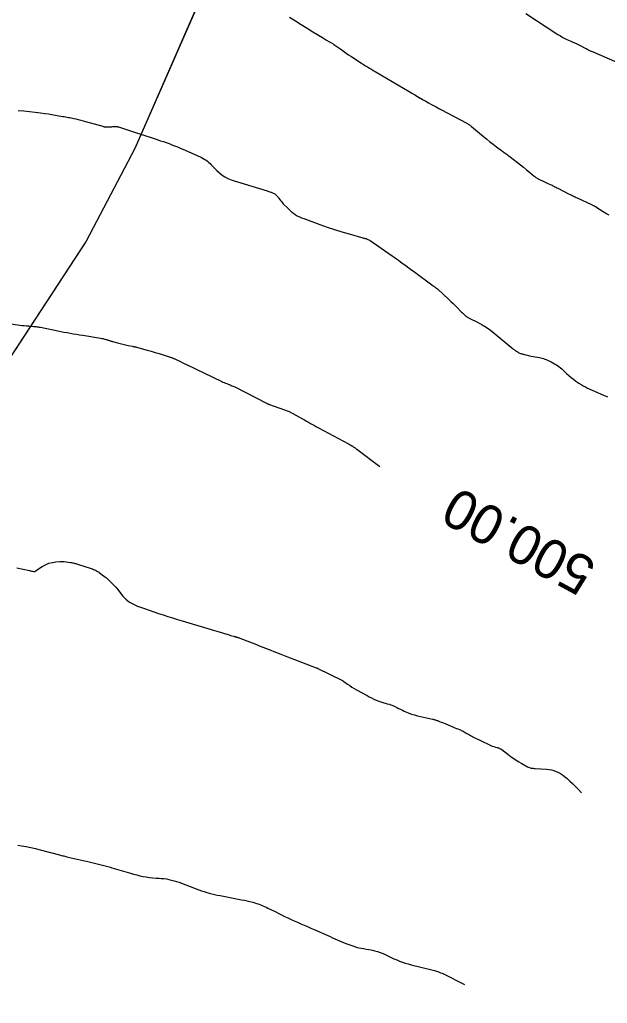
# Model space of a CAD drawing. Extents: x -629976 to -626966, y -1086511 to -1082952.
# Drawn here: x -628393.8 to -628244, y -1086175.2 to -1085924.7 of the extents above; entities that cross this region are included whole.
import ezdxf

# ---------------------------------------------------------------- set-up
doc = ezdxf.new("R2010")
doc.units = 0
for name, color, linetype in [('01_OBVOD PÚ', 7, 'Continuous'), ('01_SPRÁV_HRANICE', 7, 'Continuous'), ('01_VRSTEVNICE', 7, 'Continuous'), ('02_KULTURY STAV', 7, 'Continuous'), ('04_ZPF_OP_ORGAN', 7, 'Continuous')]:
    doc.layers.add(name, color=color, linetype=linetype)

msp = doc.modelspace()

# ---------------------------------------------------------------- linework, layer by layer
at = {"layer": '01_OBVOD PÚ'}
msp.add_lwpolyline([(-628341.94, -1085906.1), (-628364.43, -1085957.53), (-628376.86, -1085981.07), (-628416.21, -1086041.23), (-628422.26, -1086053.45), (-628443.41, -1086096.14), (-628453.2, -1086122.49), (-628455.25, -1086128.01), (-628487.12, -1086214.31), (-628510.82, -1086282.32), (-628525.65, -1086314.27), (-628531.32, -1086323.89), (-628534.4, -1086329.12), (-628536.6, -1086332.86), (-628546.36, -1086361.96)], dxfattribs=at)
at = {"layer": '01_SPRÁV_HRANICE'}
for p, q in [((-628341.94, -1085906.1), (-628364.43, -1085957.53)), ((-628364.43, -1085957.53), (-628376.86, -1085981.07)), ((-628376.86, -1085981.07), (-628416.21, -1086041.23))]:
    msp.add_line(p, q, dxfattribs=at)
at = {"layer": '01_VRSTEVNICE'}
for points in [[(-628325.01, -1085924.07), (-628323.53, -1085925.02), (-628322.03, -1085925.95), (-628320.54, -1085926.88), (-628319.03, -1085927.79), (-628316.62, -1085929.24), (-628316.09, -1085929.56), (-628315.56, -1085929.88), (-628315.02, -1085930.21), (-628314.49, -1085930.53), (-628313.93, -1085930.87), (-628313.68, -1085931.03), (-628313.43, -1085931.19), (-628313.18, -1085931.36), (-628312.93, -1085931.53), (-628312.69, -1085931.7), (-628312.45, -1085931.87), (-628312.21, -1085932.04), (-628311.96, -1085932.22), (-628311.23, -1085932.75), (-628310.61, -1085933.18), (-628309.99, -1085933.61), (-628309.37, -1085934.02), (-628308.74, -1085934.43), (-628307.12, -1085935.48), (-628306.63, -1085935.79), (-628306.14, -1085936.1), (-628305.65, -1085936.41), (-628305.15, -1085936.71), (-628304.66, -1085937.01), (-628304.16, -1085937.31), (-628303.66, -1085937.61), (-628303.16, -1085937.9), (-628294.5, -1085943.02), (-628293.81, -1085943.43), (-628293.11, -1085943.84), (-628292.41, -1085944.25), (-628291.71, -1085944.66), (-628291.63, -1085944.7), (-628290.97, -1085945.08), (-628290.3, -1085945.46), (-628289.63, -1085945.83), (-628288.96, -1085946.19), (-628288.29, -1085946.56), (-628287.62, -1085946.92), (-628286.94, -1085947.28), (-628286.27, -1085947.64), (-628280.03, -1085950.95), (-628279.85, -1085951.05), (-628279.68, -1085951.16), (-628279.5, -1085951.27), (-628279.33, -1085951.38), (-628279.16, -1085951.5), (-628279, -1085951.63), (-628278.83, -1085951.75), (-628278.67, -1085951.88), (-628275.58, -1085954.45), (-628274.76, -1085955.12), (-628273.93, -1085955.78), (-628273.09, -1085956.42), (-628272.24, -1085957.06), (-628271.02, -1085957.97), (-628270.78, -1085958.14), (-628270.54, -1085958.32), (-628270.3, -1085958.5), (-628270.06, -1085958.67), (-628269.82, -1085958.85), (-628269.58, -1085959.03), (-628269.34, -1085959.21), (-628269.1, -1085959.39), (-628266.94, -1085961.08), (-628266.17, -1085961.68), (-628265.4, -1085962.29), (-628264.64, -1085962.91), (-628263.88, -1085963.53), (-628262.64, -1085964.55), (-628262.5, -1085964.66), (-628262.36, -1085964.77), (-628262.22, -1085964.88), (-628262.08, -1085964.98), (-628261.93, -1085965.08), (-628261.78, -1085965.17), (-628261.63, -1085965.25), (-628261.47, -1085965.33), (-628260.18, -1085965.93), (-628259.84, -1085966.08), (-628259.49, -1085966.24), (-628259.15, -1085966.4), (-628258.8, -1085966.56), (-628258.62, -1085966.64), (-628258.37, -1085966.76), (-628258.12, -1085966.88), (-628257.87, -1085967.01), (-628257.62, -1085967.13), (-628257.37, -1085967.26), (-628257.12, -1085967.38), (-628256.87, -1085967.51), (-628256.62, -1085967.64), (-628253.76, -1085969.09), (-628253.51, -1085969.22), (-628253.26, -1085969.34), (-628253.01, -1085969.47), (-628252.75, -1085969.59), (-628252.5, -1085969.71), (-628252.25, -1085969.83), (-628252, -1085969.95), (-628251.74, -1085970.06), (-628248.03, -1085971.8), (-628247.9, -1085971.86), (-628247.78, -1085971.92), (-628247.65, -1085971.98), (-628247.53, -1085972.04), (-628247.36, -1085972.12), (-628247.32, -1085972.14), (-628247.28, -1085972.16), (-628247.24, -1085972.18), (-628247.2, -1085972.2), (-628247.16, -1085972.22), (-628247.11, -1085972.25), (-628247.07, -1085972.27), (-628247.03, -1085972.29), (-628246.96, -1085972.33), (-628246.89, -1085972.38), (-628246.82, -1085972.42), (-628246.74, -1085972.47), (-628246.67, -1085972.51), (-628245.12, -1085973.51), (-628244.63, -1085973.82), (-628244.15, -1085974.13), (-628243.66, -1085974.43)], [(-628264.83, -1085923.08), (-628256.92, -1085928.26), (-628256.61, -1085928.46), (-628256.29, -1085928.65), (-628255.97, -1085928.84), (-628255.65, -1085929.03), (-628255.33, -1085929.2), (-628255, -1085929.38), (-628254.66, -1085929.54), (-628254.32, -1085929.7), (-628253.47, -1085930.08), (-628252.79, -1085930.39), (-628252.11, -1085930.71), (-628251.44, -1085931.04), (-628250.77, -1085931.37), (-628249.64, -1085931.93), (-628249.54, -1085931.99), (-628249.43, -1085932.04), (-628249.33, -1085932.1), (-628249.23, -1085932.16), (-628249.12, -1085932.22), (-628249.02, -1085932.27), (-628248.92, -1085932.33), (-628248.81, -1085932.38), (-628248.7, -1085932.44), (-628248.54, -1085932.52), (-628248.37, -1085932.6), (-628248.21, -1085932.67), (-628248.04, -1085932.74), (-628239.69, -1085936.32)], [(-628394.18, -1085947.8), (-628392.74, -1085947.93), (-628391.3, -1085948.07), (-628389.87, -1085948.24), (-628388.44, -1085948.43), (-628387.34, -1085948.58), (-628386.46, -1085948.71), (-628385.58, -1085948.85), (-628384.7, -1085948.99), (-628383.82, -1085949.15), (-628382.79, -1085949.33), (-628382.43, -1085949.39), (-628382.07, -1085949.46), (-628381.72, -1085949.52), (-628381.36, -1085949.58), (-628381, -1085949.64), (-628380.65, -1085949.71), (-628380.29, -1085949.78), (-628379.94, -1085949.86), (-628379.43, -1085949.97), (-628378.83, -1085950.11), (-628378.22, -1085950.26), (-628377.62, -1085950.42), (-628377.02, -1085950.59), (-628372.62, -1085951.85), (-628372.49, -1085951.88), (-628372.37, -1085951.91), (-628372.24, -1085951.94), (-628372.11, -1085951.97), (-628371.98, -1085951.98), (-628371.85, -1085951.99), (-628371.72, -1085952), (-628371.58, -1085952), (-628371.23, -1085951.98), (-628370.92, -1085951.96), (-628370.62, -1085951.95), (-628370.31, -1085951.94), (-628370, -1085951.92), (-628369.36, -1085951.89), (-628369.26, -1085951.89), (-628369.16, -1085951.9), (-628369.06, -1085951.91), (-628368.96, -1085951.92), (-628368.86, -1085951.94), (-628368.76, -1085951.96), (-628368.66, -1085951.99), (-628368.56, -1085952.02), (-628364.22, -1085953.42), (-628362.91, -1085953.85), (-628361.61, -1085954.27), (-628360.31, -1085954.7), (-628359.01, -1085955.12), (-628357.86, -1085955.51), (-628357.14, -1085955.75), (-628356.42, -1085956), (-628355.7, -1085956.26), (-628354.99, -1085956.53), (-628354.29, -1085956.81), (-628353.58, -1085957.09), (-628352.88, -1085957.39), (-628352.19, -1085957.69), (-628347.79, -1085959.64), (-628347.4, -1085959.83), (-628347.01, -1085960.03), (-628346.63, -1085960.26), (-628346.26, -1085960.49), (-628345.91, -1085960.75), (-628345.58, -1085961.03), (-628345.26, -1085961.33), (-628344.96, -1085961.65), (-628344.9, -1085961.71), (-628344.58, -1085962.07), (-628344.24, -1085962.42), (-628343.9, -1085962.75), (-628343.55, -1085963.08), (-628342.86, -1085963.71), (-628342.18, -1085964.25), (-628341.47, -1085964.73), (-628340.71, -1085965.12), (-628339.91, -1085965.45), (-628339.08, -1085965.72), (-628338.25, -1085965.99), (-628337.42, -1085966.25), (-628336.58, -1085966.51), (-628330.74, -1085968.27), (-628330.5, -1085968.34), (-628330.26, -1085968.42), (-628330.03, -1085968.5), (-628329.79, -1085968.58), (-628329.73, -1085968.6), (-628329.53, -1085968.68), (-628329.34, -1085968.76), (-628329.15, -1085968.86), (-628328.96, -1085968.97), (-628328.78, -1085969.08), (-628328.61, -1085969.21), (-628328.45, -1085969.35), (-628328.31, -1085969.51), (-628328.3, -1085969.51), (-628328.16, -1085969.68), (-628328.02, -1085969.84), (-628327.88, -1085970.01), (-628327.75, -1085970.18), (-628327.56, -1085970.43), (-628327.33, -1085970.72), (-628327.09, -1085971), (-628326.85, -1085971.28), (-628326.59, -1085971.55), (-628325.39, -1085972.79), (-628324.96, -1085973.21), (-628324.51, -1085973.6), (-628324.04, -1085973.96), (-628323.54, -1085974.3), (-628323.03, -1085974.61), (-628322.5, -1085974.89), (-628321.96, -1085975.14), (-628321.4, -1085975.36), (-628317.27, -1085976.86), (-628315.42, -1085977.5), (-628313.57, -1085978.13), (-628311.7, -1085978.71), (-628309.83, -1085979.27), (-628306.29, -1085980.28), (-628306.17, -1085980.31), (-628306.06, -1085980.33), (-628305.95, -1085980.36), (-628305.83, -1085980.38), (-628305.72, -1085980.4), (-628305.61, -1085980.43), (-628305.49, -1085980.46), (-628305.38, -1085980.5), (-628305.22, -1085980.56), (-628305.03, -1085980.64), (-628304.84, -1085980.72), (-628304.66, -1085980.83), (-628304.49, -1085980.94), (-628298.85, -1085984.82), (-628298.31, -1085985.19), (-628297.77, -1085985.57), (-628297.24, -1085985.96), (-628296.71, -1085986.35), (-628296.38, -1085986.6), (-628296.01, -1085986.87), (-628295.65, -1085987.14), (-628295.29, -1085987.41), (-628294.92, -1085987.67), (-628294.55, -1085987.94), (-628294.19, -1085988.21), (-628293.82, -1085988.47), (-628293.46, -1085988.74), (-628288.39, -1085992.45), (-628288.27, -1085992.54), (-628288.15, -1085992.63), (-628288.03, -1085992.73), (-628287.91, -1085992.82), (-628287.71, -1085992.98), (-628287.69, -1085992.99), (-628287.68, -1085993), (-628287.66, -1085993.01), (-628287.65, -1085993.02), (-628287.63, -1085993.03), (-628287.62, -1085993.04), (-628287.6, -1085993.05), (-628287.59, -1085993.06), (-628287.57, -1085993.07), (-628287.56, -1085993.08), (-628287.54, -1085993.09), (-628287.53, -1085993.1), (-628287.44, -1085993.16), (-628287.39, -1085993.2), (-628287.33, -1085993.24), (-628287.28, -1085993.28), (-628287.23, -1085993.33), (-628284.5, -1085995.86), (-628283.89, -1085996.43), (-628283.29, -1085997.01), (-628282.7, -1085997.6), (-628282.12, -1085998.19), (-628281.44, -1085998.89), (-628281.2, -1085999.14), (-628280.96, -1085999.38), (-628280.71, -1085999.62), (-628280.45, -1085999.85), (-628280.19, -1086000.09), (-628280.06, -1086000.2), (-628279.93, -1086000.3), (-628279.8, -1086000.39), (-628279.66, -1086000.48), (-628279.52, -1086000.57), (-628279.37, -1086000.65), (-628279.23, -1086000.73), (-628279.08, -1086000.8), (-628277.08, -1086001.77), (-628275.96, -1086002.37), (-628274.87, -1086003.02), (-628273.83, -1086003.75), (-628272.82, -1086004.53), (-628268.37, -1086008.26), (-628268.09, -1086008.49), (-628267.8, -1086008.72), (-628267.5, -1086008.93), (-628267.19, -1086009.13), (-628266.93, -1086009.31), (-628266.75, -1086009.41), (-628266.57, -1086009.51), (-628266.38, -1086009.6), (-628266.18, -1086009.68), (-628265.98, -1086009.75), (-628265.78, -1086009.81), (-628265.58, -1086009.87), (-628265.38, -1086009.92), (-628264.84, -1086010.05), (-628264.36, -1086010.16), (-628263.88, -1086010.27), (-628263.41, -1086010.37), (-628262.93, -1086010.46), (-628261.32, -1086010.75), (-628260.97, -1086010.82), (-628260.63, -1086010.9), (-628260.29, -1086011.01), (-628259.95, -1086011.13), (-628259.62, -1086011.26), (-628259.3, -1086011.4), (-628258.97, -1086011.54), (-628258.65, -1086011.7), (-628258.32, -1086011.86), (-628257.92, -1086012.08), (-628257.52, -1086012.3), (-628257.12, -1086012.54), (-628256.74, -1086012.78), (-628256.36, -1086013.05), (-628256, -1086013.32), (-628255.65, -1086013.62), (-628255.31, -1086013.93), (-628254.41, -1086014.78), (-628253.84, -1086015.3), (-628253.25, -1086015.8), (-628252.64, -1086016.28), (-628252.02, -1086016.74), (-628251.79, -1086016.9), (-628251.26, -1086017.25), (-628250.73, -1086017.59), (-628250.18, -1086017.91), (-628249.62, -1086018.22), (-628249.06, -1086018.5), (-628248.49, -1086018.78), (-628247.91, -1086019.04), (-628247.33, -1086019.3), (-628244.82, -1086020.38), (-628244.55, -1086020.5), (-628244.29, -1086020.61), (-628244.02, -1086020.73)], [(-628396.64, -1086002.07), (-628393.75, -1086002.47), (-628393.17, -1086002.54), (-628392.6, -1086002.6), (-628392.02, -1086002.65), (-628391.44, -1086002.7), (-628390.88, -1086002.74), (-628390.58, -1086002.76), (-628390.28, -1086002.79), (-628389.98, -1086002.81), (-628389.69, -1086002.85), (-628389.39, -1086002.88), (-628389.09, -1086002.93), (-628388.8, -1086002.98), (-628388.5, -1086003.03), (-628384.09, -1086003.94), (-628383.3, -1086004.1), (-628382.5, -1086004.25), (-628381.71, -1086004.39), (-628380.91, -1086004.53), (-628380.11, -1086004.67), (-628379.32, -1086004.8), (-628378.52, -1086004.93), (-628377.72, -1086005.06), (-628373.15, -1086005.8), (-628372.87, -1086005.85), (-628372.6, -1086005.91), (-628372.33, -1086005.98), (-628372.06, -1086006.05), (-628371.79, -1086006.13), (-628371.65, -1086006.17), (-628371.52, -1086006.22), (-628371.39, -1086006.26), (-628371.25, -1086006.3), (-628371.12, -1086006.34), (-628370.98, -1086006.39), (-628370.85, -1086006.43), (-628370.72, -1086006.47), (-628370.66, -1086006.49), (-628370.49, -1086006.54), (-628370.33, -1086006.59), (-628370.17, -1086006.63), (-628370, -1086006.68), (-628368.83, -1086007.02), (-628368.16, -1086007.2), (-628367.48, -1086007.36), (-628366.81, -1086007.52), (-628366.13, -1086007.66), (-628365.01, -1086007.87), (-628364.89, -1086007.89), (-628364.76, -1086007.92), (-628364.64, -1086007.94), (-628364.52, -1086007.97), (-628364.4, -1086007.99), (-628364.28, -1086008.02), (-628364.16, -1086008.05), (-628364.04, -1086008.08), (-628361.3, -1086008.85), (-628360.28, -1086009.15), (-628359.26, -1086009.45), (-628358.24, -1086009.75), (-628357.22, -1086010.07), (-628355.44, -1086010.63), (-628355.31, -1086010.67), (-628355.18, -1086010.71), (-628355.06, -1086010.76), (-628354.93, -1086010.81), (-628354.8, -1086010.85), (-628354.68, -1086010.91), (-628354.56, -1086010.96), (-628354.43, -1086011.02), (-628353.54, -1086011.43), (-628352.96, -1086011.7), (-628352.4, -1086011.97), (-628351.83, -1086012.24), (-628351.26, -1086012.51), (-628342.3, -1086016.83), (-628341.99, -1086016.98), (-628341.67, -1086017.12), (-628341.35, -1086017.25), (-628341.02, -1086017.38), (-628340.84, -1086017.45), (-628340.61, -1086017.54), (-628340.37, -1086017.64), (-628340.14, -1086017.73), (-628339.9, -1086017.82), (-628339.67, -1086017.92), (-628339.44, -1086018.02), (-628339.21, -1086018.12), (-628338.98, -1086018.24), (-628330.86, -1086022.37), (-628330.77, -1086022.42), (-628330.67, -1086022.47), (-628330.57, -1086022.51), (-628330.48, -1086022.55), (-628330.38, -1086022.6), (-628330.28, -1086022.64), (-628330.18, -1086022.67), (-628330.08, -1086022.71), (-628325.07, -1086024.46), (-628321.68, -1086026.36), (-628321.17, -1086026.64), (-628320.66, -1086026.93), (-628320.16, -1086027.22), (-628319.65, -1086027.5), (-628319.14, -1086027.79), (-628318.63, -1086028.07), (-628318.11, -1086028.35), (-628317.6, -1086028.63), (-628309.99, -1086032.73), (-628309.78, -1086032.84), (-628309.57, -1086032.96), (-628309.37, -1086033.08), (-628309.16, -1086033.2), (-628309.08, -1086033.25), (-628308.92, -1086033.34), (-628308.76, -1086033.44), (-628308.6, -1086033.55), (-628308.45, -1086033.65), (-628308.29, -1086033.76), (-628308.14, -1086033.87), (-628307.99, -1086033.98), (-628307.84, -1086034.09), (-628302, -1086038.48)], [(-628394.53, -1086064.27), (-628391.31, -1086064.98), (-628391.1, -1086065.02), (-628390.9, -1086065.07), (-628390.7, -1086065.12), (-628390.5, -1086065.16), (-628390.21, -1086065.23), (-628390.15, -1086065.25), (-628390.09, -1086065.25), (-628390.03, -1086065.26), (-628389.97, -1086065.26), (-628389.91, -1086065.25), (-628389.85, -1086065.24), (-628389.8, -1086065.21), (-628389.75, -1086065.17), (-628389.72, -1086065.14), (-628389.65, -1086065.08), (-628389.59, -1086065.03), (-628389.52, -1086064.98), (-628389.45, -1086064.93), (-628388.01, -1086063.96), (-628387.19, -1086063.5), (-628386.34, -1086063.13), (-628385.45, -1086062.9), (-628384.52, -1086062.77), (-628383.54, -1086062.7), (-628383.01, -1086062.69), (-628382.47, -1086062.7), (-628381.94, -1086062.75), (-628381.4, -1086062.82), (-628380.79, -1086062.93), (-628380.56, -1086062.97), (-628380.34, -1086063.01), (-628380.12, -1086063.06), (-628379.9, -1086063.11), (-628379.68, -1086063.16), (-628379.47, -1086063.22), (-628379.25, -1086063.28), (-628379.03, -1086063.35), (-628375.53, -1086064.49), (-628375.26, -1086064.58), (-628374.99, -1086064.69), (-628374.72, -1086064.8), (-628374.46, -1086064.92), (-628374.21, -1086065.06), (-628373.96, -1086065.2), (-628373.72, -1086065.35), (-628373.48, -1086065.51), (-628372.72, -1086066.05), (-628372.19, -1086066.46), (-628371.67, -1086066.88), (-628371.17, -1086067.32), (-628370.68, -1086067.78), (-628370.21, -1086068.26), (-628369.76, -1086068.75), (-628369.31, -1086069.25), (-628368.88, -1086069.77), (-628367.48, -1086071.47), (-628367.1, -1086071.9), (-628366.69, -1086072.3), (-628366.25, -1086072.67), (-628365.78, -1086073), (-628365.29, -1086073.31), (-628364.78, -1086073.58), (-628364.26, -1086073.82), (-628363.73, -1086074.03), (-628362, -1086074.65), (-628360.81, -1086075.08), (-628359.61, -1086075.49), (-628358.41, -1086075.9), (-628357.2, -1086076.3), (-628356, -1086076.69), (-628354.79, -1086077.07), (-628353.58, -1086077.44), (-628352.36, -1086077.81), (-628341.01, -1086081.2), (-628340.68, -1086081.3), (-628340.35, -1086081.4), (-628340.02, -1086081.49), (-628339.69, -1086081.59), (-628339.2, -1086081.73), (-628339.12, -1086081.75), (-628339.03, -1086081.77), (-628338.94, -1086081.8), (-628338.86, -1086081.82), (-628338.77, -1086081.84), (-628338.68, -1086081.86), (-628338.59, -1086081.89), (-628338.51, -1086081.91), (-628338.33, -1086081.96), (-628338.16, -1086082.01), (-628337.99, -1086082.07), (-628337.82, -1086082.13), (-628337.65, -1086082.19), (-628335.25, -1086083.13), (-628333.89, -1086083.67), (-628332.52, -1086084.21), (-628331.15, -1086084.75), (-628329.79, -1086085.29), (-628329.01, -1086085.59), (-628327.26, -1086086.28), (-628325.5, -1086086.96), (-628323.74, -1086087.63), (-628321.98, -1086088.3), (-628318.19, -1086089.72), (-628318.14, -1086089.74), (-628318.09, -1086089.76), (-628318.04, -1086089.78), (-628317.99, -1086089.8), (-628317.94, -1086089.82), (-628317.89, -1086089.84), (-628317.85, -1086089.86), (-628317.8, -1086089.89), (-628311.68, -1086092.93), (-628311.62, -1086092.96), (-628311.56, -1086092.99), (-628311.5, -1086093.03), (-628311.44, -1086093.07), (-628311.38, -1086093.1), (-628311.32, -1086093.14), (-628311.27, -1086093.18), (-628311.21, -1086093.22), (-628310.23, -1086093.92), (-628309.67, -1086094.3), (-628309.11, -1086094.66), (-628308.54, -1086095.01), (-628307.96, -1086095.35), (-628305.25, -1086096.85), (-628304.69, -1086097.15), (-628304.11, -1086097.44), (-628303.53, -1086097.71), (-628302.95, -1086097.96), (-628302.29, -1086098.24), (-628302.03, -1086098.35), (-628301.76, -1086098.44), (-628301.49, -1086098.53), (-628301.22, -1086098.61), (-628300.95, -1086098.69), (-628300.67, -1086098.76), (-628300.4, -1086098.84), (-628300.12, -1086098.92), (-628299.66, -1086099.04), (-628299.16, -1086099.2), (-628298.67, -1086099.38), (-628298.19, -1086099.59), (-628297.72, -1086099.82), (-628297.7, -1086099.84), (-628297.22, -1086100.09), (-628296.74, -1086100.33), (-628296.26, -1086100.57), (-628295.77, -1086100.79), (-628295.34, -1086100.98), (-628294.62, -1086101.28), (-628293.9, -1086101.55), (-628293.16, -1086101.77), (-628292.41, -1086101.96), (-628288.61, -1086102.83), (-628288.44, -1086102.87), (-628288.27, -1086102.91), (-628288.11, -1086102.95), (-628287.94, -1086102.99), (-628287.78, -1086103.04), (-628287.61, -1086103.09), (-628287.45, -1086103.15), (-628287.29, -1086103.21), (-628286.81, -1086103.4), (-628286.41, -1086103.56), (-628286.01, -1086103.72), (-628285.62, -1086103.89), (-628285.22, -1086104.05), (-628283.23, -1086104.87), (-628282.86, -1086105.02), (-628282.48, -1086105.18), (-628282.11, -1086105.33), (-628281.73, -1086105.48), (-628281.48, -1086105.59), (-628281.24, -1086105.7), (-628280.99, -1086105.81), (-628280.75, -1086105.93), (-628280.51, -1086106.06), (-628280.27, -1086106.2), (-628280.04, -1086106.33), (-628279.81, -1086106.47), (-628279.57, -1086106.61), (-628279.46, -1086106.69), (-628279.16, -1086106.86), (-628278.87, -1086107.03), (-628278.56, -1086107.19), (-628278.26, -1086107.34), (-628274.08, -1086109.35), (-628273.71, -1086109.52), (-628273.33, -1086109.67), (-628272.95, -1086109.81), (-628272.56, -1086109.93), (-628272.09, -1086110.07), (-628271.93, -1086110.12), (-628271.78, -1086110.17), (-628271.63, -1086110.22), (-628271.47, -1086110.28), (-628271.33, -1086110.35), (-628271.18, -1086110.42), (-628271.05, -1086110.5), (-628270.91, -1086110.6), (-628269.36, -1086111.79), (-628268.5, -1086112.42), (-628267.62, -1086113.03), (-628266.71, -1086113.6), (-628265.79, -1086114.14), (-628264.35, -1086114.95), (-628264.13, -1086115.06), (-628263.9, -1086115.16), (-628263.67, -1086115.23), (-628263.43, -1086115.28), (-628263.18, -1086115.32), (-628262.94, -1086115.35), (-628262.69, -1086115.38), (-628262.44, -1086115.4), (-628259.53, -1086115.59), (-628258.9, -1086115.66), (-628258.28, -1086115.77), (-628257.67, -1086115.93), (-628257.07, -1086116.13), (-628256.49, -1086116.39), (-628255.93, -1086116.68), (-628255.41, -1086117.03), (-628254.91, -1086117.42), (-628254.3, -1086117.94), (-628253.57, -1086118.6), (-628252.86, -1086119.26), (-628252.16, -1086119.95), (-628251.48, -1086120.65), (-628250.59, -1086121.59)], [(-628394.25, -1086134.9), (-628393.27, -1086135.06), (-628392.08, -1086135.28), (-628390.9, -1086135.51), (-628389.73, -1086135.79), (-628388.56, -1086136.08), (-628383.62, -1086137.41), (-628383.35, -1086137.48), (-628383.08, -1086137.55), (-628382.81, -1086137.62), (-628382.54, -1086137.68), (-628382.26, -1086137.75), (-628381.99, -1086137.82), (-628381.72, -1086137.88), (-628381.45, -1086137.94), (-628376.05, -1086139.17), (-628374.69, -1086139.5), (-628373.32, -1086139.84), (-628371.97, -1086140.2), (-628370.61, -1086140.57), (-628370.3, -1086140.66), (-628369.11, -1086141), (-628367.91, -1086141.35), (-628366.72, -1086141.71), (-628365.53, -1086142.06), (-628364.74, -1086142.3), (-628363.94, -1086142.52), (-628363.13, -1086142.72), (-628362.32, -1086142.88), (-628361.5, -1086143.01), (-628360.68, -1086143.12), (-628359.86, -1086143.21), (-628359.03, -1086143.29), (-628358.2, -1086143.35), (-628357.7, -1086143.38), (-628357.04, -1086143.44), (-628356.38, -1086143.53), (-628355.73, -1086143.65), (-628355.08, -1086143.8), (-628354.44, -1086143.98), (-628353.8, -1086144.17), (-628353.17, -1086144.39), (-628352.54, -1086144.61), (-628348.11, -1086146.29), (-628347.45, -1086146.53), (-628346.79, -1086146.75), (-628346.12, -1086146.96), (-628345.45, -1086147.14), (-628344.77, -1086147.32), (-628344.09, -1086147.48), (-628343.41, -1086147.62), (-628342.72, -1086147.76), (-628337.21, -1086148.82), (-628336.5, -1086148.96), (-628335.79, -1086149.12), (-628335.09, -1086149.29), (-628334.39, -1086149.47), (-628333.85, -1086149.62), (-628333.42, -1086149.75), (-628333, -1086149.88), (-628332.59, -1086150.03), (-628332.17, -1086150.2), (-628331.77, -1086150.37), (-628331.36, -1086150.55), (-628330.96, -1086150.74), (-628330.56, -1086150.93), (-628328.71, -1086151.86), (-628327.9, -1086152.26), (-628327.09, -1086152.66), (-628326.27, -1086153.05), (-628325.45, -1086153.44), (-628324.63, -1086153.82), (-628323.81, -1086154.19), (-628322.98, -1086154.56), (-628322.15, -1086154.92), (-628322.11, -1086154.94), (-628321.26, -1086155.31), (-628320.41, -1086155.68), (-628319.56, -1086156.05), (-628318.71, -1086156.42), (-628315.21, -1086157.96), (-628314.62, -1086158.22), (-628314.03, -1086158.49), (-628313.44, -1086158.76), (-628312.85, -1086159.04), (-628312.25, -1086159.31), (-628311.66, -1086159.56), (-628311.05, -1086159.8), (-628310.44, -1086160.03), (-628308.63, -1086160.67), (-628308.01, -1086160.87), (-628307.39, -1086161.04), (-628306.76, -1086161.18), (-628306.12, -1086161.28), (-628305.47, -1086161.38), (-628304.83, -1086161.49), (-628304.2, -1086161.62), (-628303.56, -1086161.76), (-628303.34, -1086161.81), (-628302.61, -1086162.01), (-628301.89, -1086162.25), (-628301.19, -1086162.53), (-628300.5, -1086162.85), (-628299.79, -1086163.21), (-628299.1, -1086163.54), (-628298.4, -1086163.86), (-628297.69, -1086164.16), (-628296.98, -1086164.44), (-628296.25, -1086164.7), (-628295.53, -1086164.94), (-628294.79, -1086165.16), (-628294.05, -1086165.36), (-628288.75, -1086166.65), (-628288.37, -1086166.75), (-628287.99, -1086166.86), (-628287.62, -1086166.98), (-628287.24, -1086167.11), (-628286.88, -1086167.25), (-628286.51, -1086167.4), (-628286.15, -1086167.56), (-628285.8, -1086167.73), (-628280.45, -1086170.43)]]:
    msp.add_lwpolyline(points, dxfattribs=at)
at = {"layer": '02_KULTURY STAV'}
msp.add_lwpolyline([(-628341.94, -1085906.1), (-628364.43, -1085957.53), (-628376.86, -1085981.07), (-628416.21, -1086041.23), (-628422.26, -1086053.45), (-628443.41, -1086096.14), (-628453.2, -1086122.49), (-628455.25, -1086128.01), (-628487.12, -1086214.31), (-628510.82, -1086282.32), (-628525.65, -1086314.27), (-628531.32, -1086323.89), (-628534.4, -1086329.12), (-628536.6, -1086332.86), (-628544.68, -1086356.94)], dxfattribs=at)
at = {"layer": '04_ZPF_OP_ORGAN'}
msp.add_lwpolyline([(-628341.94, -1085906.1), (-628364.43, -1085957.53), (-628376.86, -1085981.07), (-628416.21, -1086041.23), (-628422.26, -1086053.45), (-628443.41, -1086096.14), (-628453.2, -1086122.49), (-628455.25, -1086128.01), (-628487.12, -1086214.31), (-628510.82, -1086282.32), (-628525.65, -1086314.27), (-628531.32, -1086323.89), (-628534.4, -1086329.12), (-628536.6, -1086332.86), (-628544.67, -1086356.94)], dxfattribs=at)

# ---------------------------------------------------------------- texts
at = {"layer": '01_VRSTEVNICE'}
msp.add_text('500.00', height=10, rotation=151.5655, dxfattribs=at).set_placement((-628246.31, -1086062.95))

doc.saveas('drawing.dxf')
